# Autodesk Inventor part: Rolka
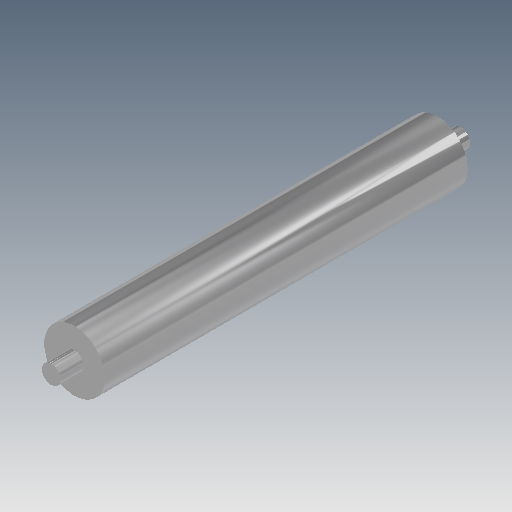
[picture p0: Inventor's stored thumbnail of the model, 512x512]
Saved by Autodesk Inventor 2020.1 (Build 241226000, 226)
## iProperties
Created: 2005-09
Part Number: Rolka
Document SubType Name: Modeling
Description: Rolka
Density: 1 g/cm^3
Material: Ogólny
Appearance: Chrom
Designer: F.Stasiak
Manager: www.cadconsulting.pl
Company: Fabian Stasiak CAD Consulting
Author: F.Stasiak
Subject: Zbiór ćwiczeń. Autodesk Inventor 2020. Kurs podstawowy
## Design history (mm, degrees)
sketch "Szkic1"
  geometry: C1 r 20 at (-75, 150)
  constraints: 1 centre point
  dimensions: "d5" = 40 diameter of C1
extrude "Wyciągnięcie proste1" new body sketch "Szkic1" distance "d0" = 50; taper "d1" = 0 deg
sketch "Szkic2"
  geometry: C1 r 20 at (0, 0) reference; C2 r 65 at (0, 0)
  constraints: 1 centre point, 1 coincident
  dimensions: "d2" = 130 diameter of C2
extrude "Wyciągnięcie proste2" join sketch "Szkic2" distance "d3" = 780; taper "d4" = 0 deg
sketch "Szkic3"
  geometry: C1 r 65 at (0, 0) reference; C2 r 20 at (0, 0)
  constraints: 1 centre point, 1 coincident
  dimensions: "d6" = 40 diameter of C2 (= d5)
extrude "Wyciągnięcie proste3" join sketch "Szkic3" distance "d7" = 50 (= d0); taper "d8" = 0 deg
node "Bryła1"
node "Korpusy bryłowe"
node "Korpusy powierzchniowe"
node "Pętla rzutowana1"
node "Pętla rzutowana2"
